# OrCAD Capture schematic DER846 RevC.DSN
size B; title: DER 846; rev: B
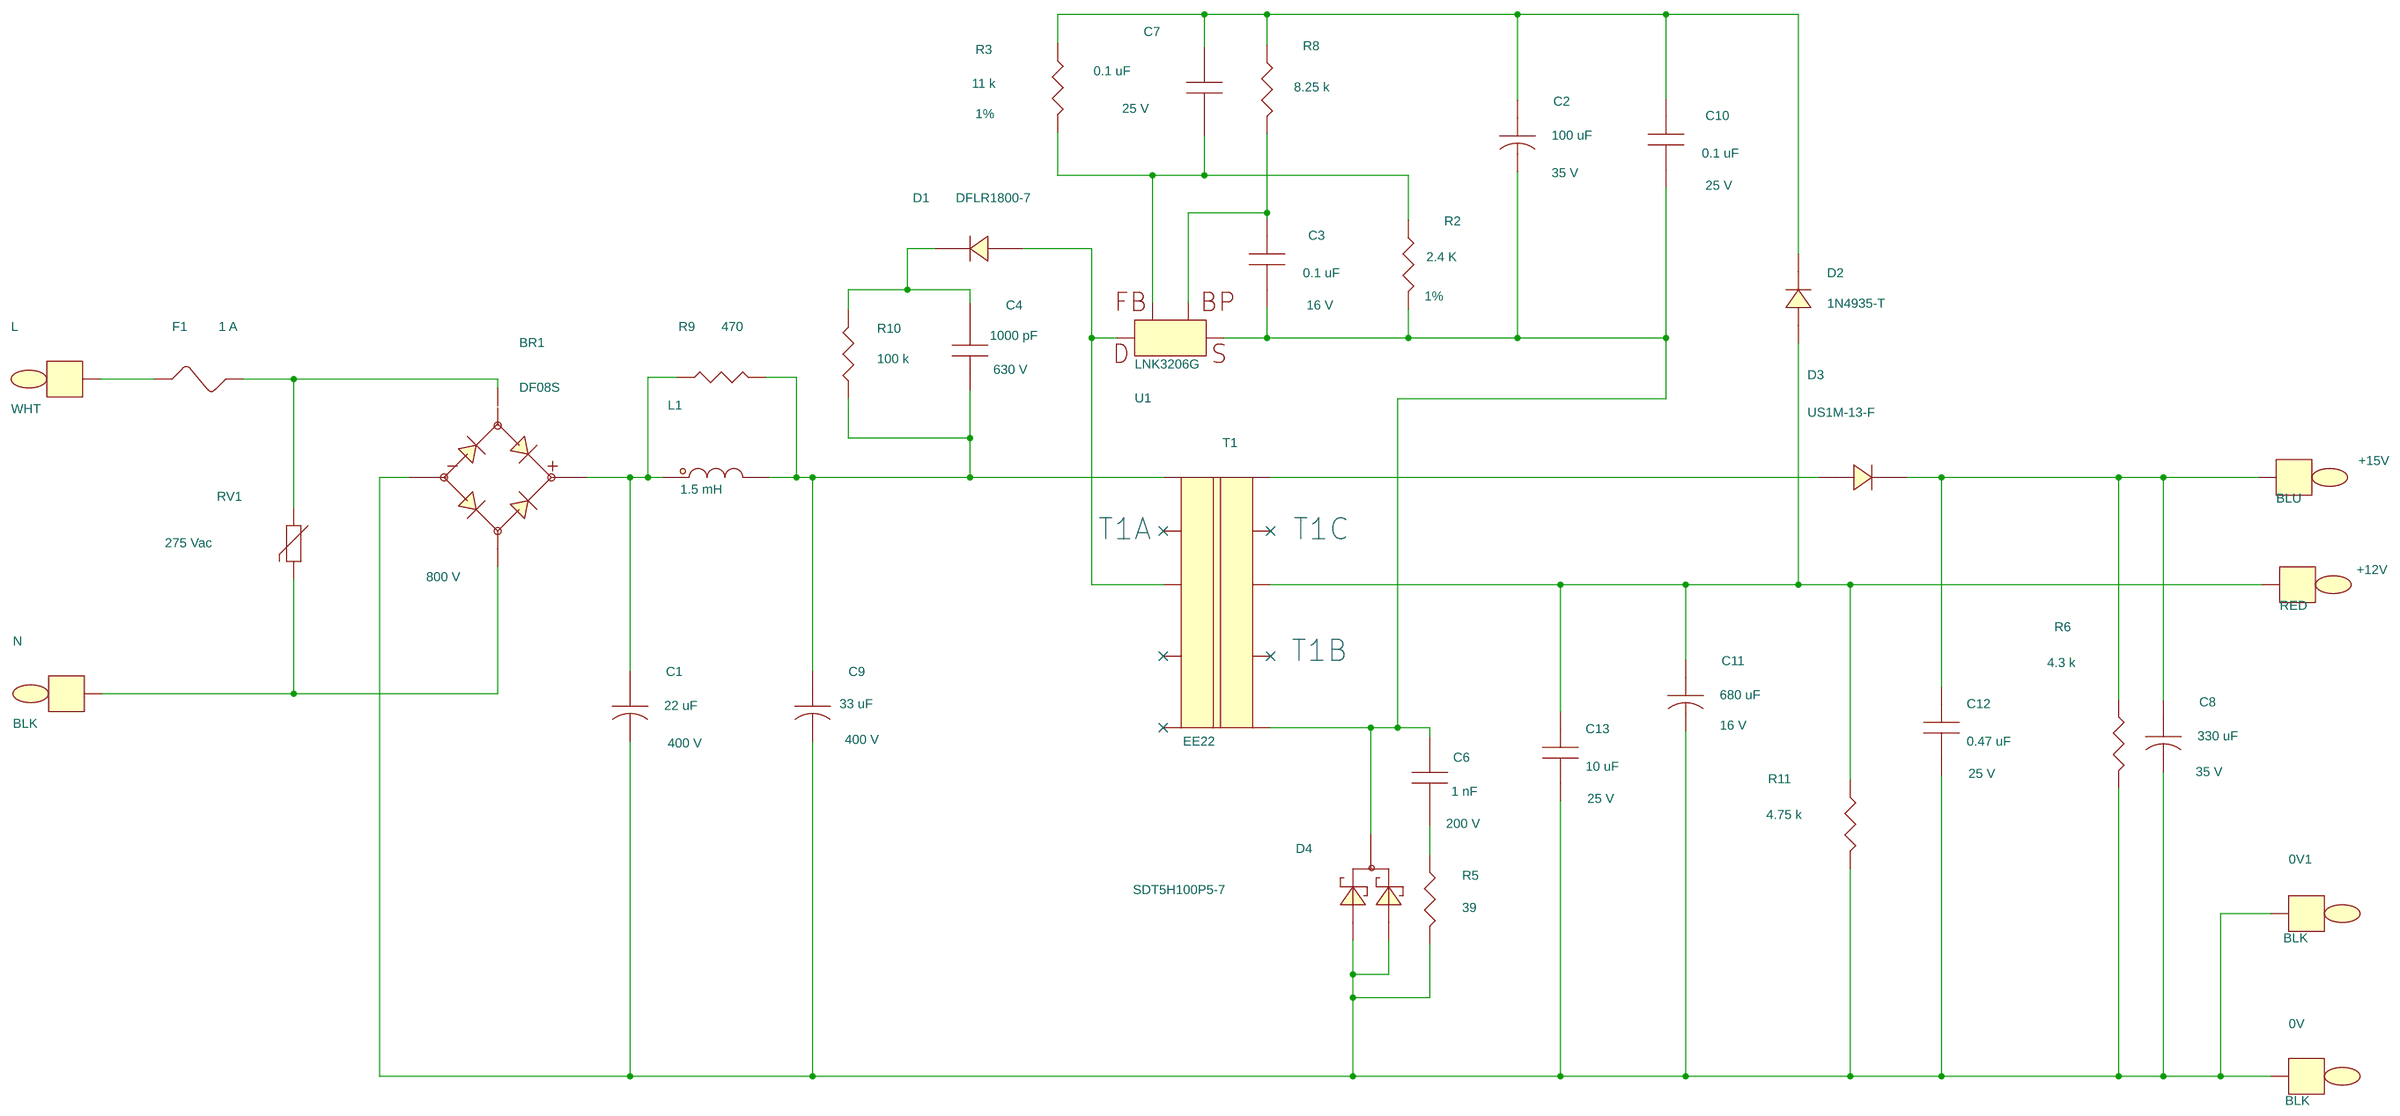
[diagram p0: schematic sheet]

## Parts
0V  BLK  [pitpkeystone125x125]
0V1  BLK  [pitpkeystone125x125]
+12V  RED  [pitpkeystone125x125]
+15V  BLU  [pitpkeystone125x125]
BR1  DF08S  [pismddfs]
C1  22 uF  [pipolcapcyld400ls200040]
C2  100 uF  [pipolcapcyld250ls100030]
C3  0.1 uF  [pismc0805]
C4  1000 pF  [pismc1206]
C6  1 nF  [pismc1206]
C7  0.1 uF  [pismc0603]
C8  330 uF  [pipolcapcyld400ls200040]
C9  33 uF  [pipolcapclyd630ls300040]
C10  0.1 uF  [pismc0603]
C11  680 uF  [pipolcapcyld400ls200040]
C12  0.47 uF  [pismc0805]
C13  10 uF  [pismc1206]
D1  DFLR1800-7  [pismddflr120012]
D2  1N4935-T  [pidv200x110x040do41]
D3  US1M-13-F  [pismdsma]
D4  SDT5H100P5-7  [pismdpowerdi5]
F1  1 A  [pi_rst_microfuse]
L  WHT  [pitpkeystone125x125]
L1  1.5 mH  [pi_choke_RLB9012_D2]
N  BLK  [pitpkeystone125x125]
R2  2.4 K  [pismr0603]
R3  11 k  [pismr0603]
R5  39  [pismr1206]
R6  4.3 k  [pismr1206]
R8  8.25 k  [pismr1206]
R9  470  [pismr1206]
R10  100 k  [pismr1206]
R11  4.75 k  [pismr1206]
RV1  275 Vac  [pidisc350x160ls210x140040]
T1  EE22  [pibobbinee22v10ptdk]
U1  LNK3206G  [piicsmd8cshort5678]

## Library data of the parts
0V 0V1 N = TESTPOINT: Part Number: 35-00042-00
+12V = TESTPOINT: Part Number: 35-00043-00
+15V = TESTPOINT: Part Number: 35-00185-00
BR1 = DIODE_BRIDGE_+-~~: Disp_Voltage: 800 V; Part Number: 15-00730-00
C1 = CAP_POL: ALT_SYMBOLS: pipolcapclyd12p5x20ls5d40h; Disp_Voltage: 400 V; FPLIST: pipolcapcyld400ls200040,pipolcapclyd12p5x20ls5d40h; Part Number: 20-00827-00; Voltage: 400 V
C2 = CAP_POL: ALT_SYMBOLS: pipolcapcyld250ls100030h; Disp_Voltage: 35 V; FPLIST: pipolcapcyld250ls100030,pipolcapcyld250ls100030h; Part Number: 20-00437-00; Voltage: 35 V
C3 = CAP_NP: Disp_Voltage: 16 V; Part Number: 20-09164-00; Voltage: 16 V
C4 = CAP_NP: Disp_Voltage: 630 V; Part Number: 20-08616-00; Voltage: 630 V
C6 = CAP_NP: Disp_Voltage: 200 V; Part Number: 24-00024-00; Voltage: 200 V
C7 C10 = CAP_NP: Disp_Voltage: 25 V; Part Number: 20-09165-00; Voltage: 25 V
C8 = CAP_POL: ALT_SYMBOLS: pipolcapclyd395x630ls200030h; Disp_Voltage: 35 V; FPLIST: pipolcapcyld400ls200040,pipolcapclyd395x630ls200030h; Part Number: 20-00122-00; Voltage: 35 V
C9 = CAP_POL: ALT_SYMBOLS: pipolcapclyd630ls300040800h; Disp_Voltage: 400 V; FPLIST: pipolcapclyd630ls300040,pipolcapclyd630ls300040800h; Part Number: 20-00487-00; Voltage: 400 V
C11 = CAP_POL: ALT_SYMBOLS: pipolcapclyd10d14h030H; Disp_Voltage: 16 V; FPLIST: pipolcapcyld400ls200040,pipolcapclyd10d14h030H; Part Number: 20-09087-00; Voltage: 16 V
C12 = CAP_NP: Disp_Voltage: 25 V; Part Number: 20-09182-00; Voltage: 25 V
C13 = CAP_NP: Disp_Voltage: 25 V; Part Number: 20-08608-00; Voltage: 25 V
D1 = DIODE: Part Number: 15-00919-00
D2 = DIODE: ALT_SYMBOLS: pidax475x125040do41,pidv200x110x040do41wbead,pidax390x125040do41; FPLIST: pidv200x110x040do41,pidax475x125040do41,pidv200x110x040do41wbead,pidax390x125040do41; Part Number: 15-00801-00
D3 = DIODE: Part Number: 15-00957-00
D4 = DS_DUAL_CK_A_AC: Part Number: 15-01327-00
F1 = FUSE: ALT_SYMBOLS: pirstmicrofusehoz; FPLIST: pi_rst_microfuse,pirstmicrofusehoz; Part Number: 40-00053-00
L = TESTPOINT: Part Number: 35-00044-00
L1 = INDUCTOR_DOT2: Part Number: 30-00423-00
R2 = R: Disp_Tol: 1%; Part Number: 05-06488-00
R3 = R: Disp_Tol: 1%; Part Number: 05-03186-00
R5 = R: Part Number: 05-01318-00
R6 = R: Part Number: 05-01367-00
R8 = R: Disp_Tol: 1%; Part Number: 05-00281-00
R9 = R: Part Number: 05-01344-00
R10 = R: Part Number: 05-01400-00
R11 = R: Disp_Tol: 1%; Part Number: 05-00258-00
RV1 = VARISTOR: ALT_SYMBOLS: pi_disc_354x220_ls220x10_040_h; FPLIST: pidisc350x160ls210x140040,pi_disc_354x220_ls220x10_040_h; Part Number: 85-00015-00
T1 = BEEL22_10P_GENERIC: Part Number: 25-00895-00
U1 = LNK32XX_8C: Part Number: 10-00982-00

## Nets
SOURCE: U1.6(SOURCE) U1.7(SOURCE) U1.8(SOURCE)
N00464: BR1.1 C1.1 L1.2 R9.1
N01028: C4.1 C9.1 L1.1 R9.2 R10.1 T1.1
N02503: BR1.3 F1.2 RV1.1
N04889: D1.2 T1.3 U1.4(D)
N05128: C3.1 R8.2 U1.1(BP)
N05532: C2.2 C3.2 C6.1 C10.2 D4.2(K) R2.2 T1.6 U1.5(S)
N05805: C2.1 C7.1 C10.1 D2.1 R3.1 R8.1
N06465: C7.2 R2.1 R3.2 U1.2(FB)
N09220: 0V.1 0V1.1 BR1.2 C1.2 C8.2 C9.2 C11.2 C12.2 C13.2 D4.1(A1) D4.3(A2) R5.2 R6.2 R11.2
N11458: C4.2 D1.1 R10.2
N14333: F1.1 L.1
N14338: BR1.4 N.1 RV1.2
N20013: +12V.1 C11.1 C13.1 D2.2 R11.1 T1.8
N47720: +15V.1 C8.1 C12.1 D3.1 R6.1
N56683: D3.2 T1.10
N60111: C6.2 R5.1

Not connected (* = marked no-connect by the designer): T1 2* 4* 5* 7* 9*

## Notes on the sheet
- T1A
- T1C
- T1B
